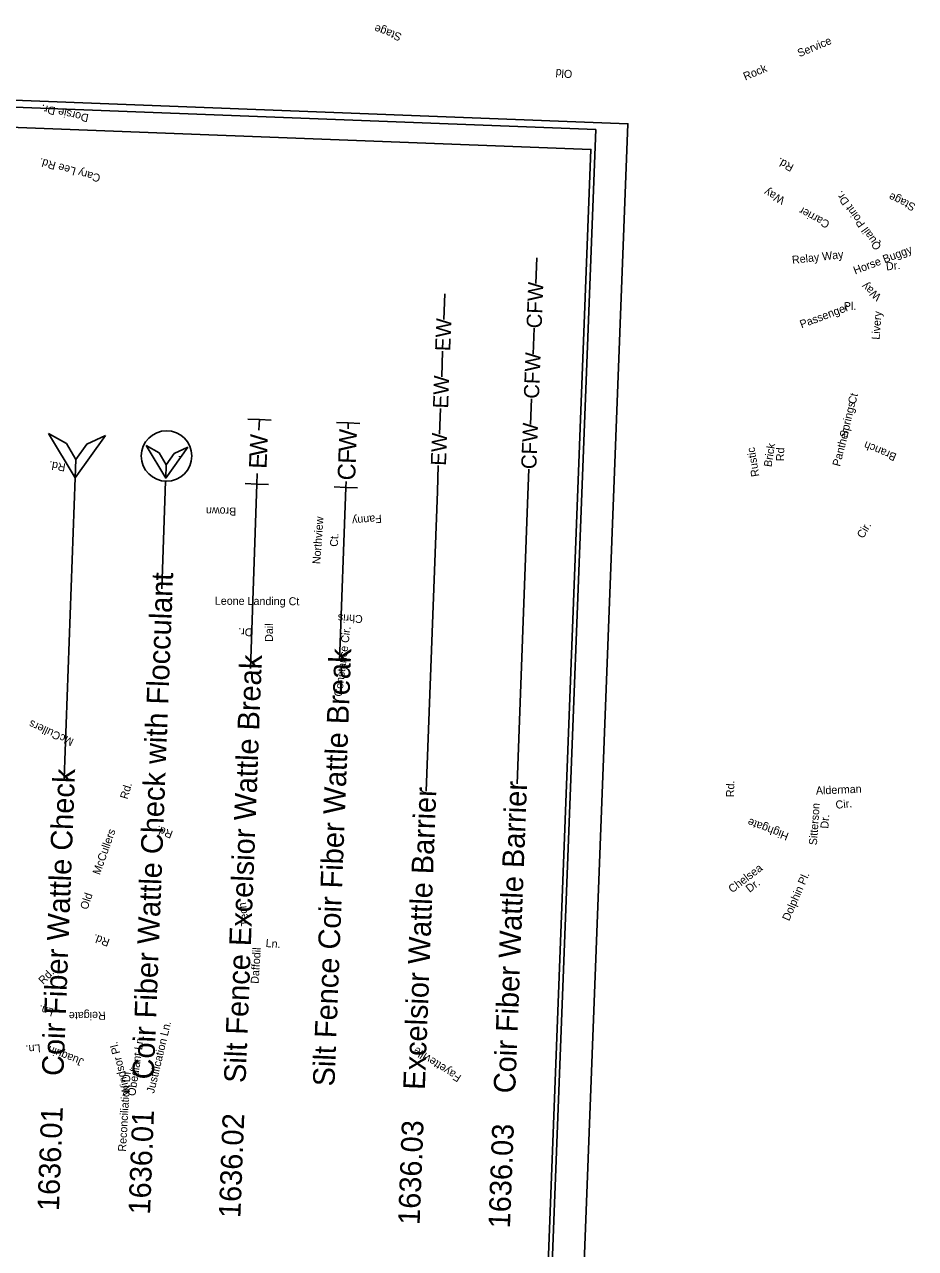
# Model space of a CAD drawing. Extents: x 1654773 to 2116434, y 680831 to 888488.
# Drawn here: x 2113644 to 2116434, y 697117 to 700949 of the extents above; entities that cross this region are included whole.
import ezdxf

# ---------------------------------------------------------------- set-up
doc = ezdxf.new("R2010")
doc.units = 0
for name, color, linetype in [('EC Title Sheet CELL', 7, 'Continuous'), ('Exist Road Non-System Type 51 Label', 7, 'Continuous'), ('Exist Road Primary US Label', 7, 'Continuous'), ('Exist Road Secondary Type 51 Label', 7, 'Continuous'), ('Old_Level_61', 7, 'Continuous'), ('Scratch_Level_6', 7, 'Continuous'), ('Sheet Plot Border Inside CELL', 7, 'Continuous'), ('Sheet Plot Border Outside CELL', 7, 'Continuous')]:
    doc.layers.add(name, color=color, linetype=linetype)

msp = doc.modelspace()

# ---------------------------------------------------------------- linework, layer by layer
at = {"layer": 'EC Title Sheet CELL'}
for p, q in [((2113767.7, 698588.4), (2113802.9, 699529.8)), ((2114073.8, 699182), (2114085.8, 699518.9)), ((2114352.1, 698932.5), (2114371.8, 699510)), ((2114630.7, 698956.7), (2114650.1, 699499.3)), ((2114901.9, 698548.4), (2114936.7, 699486.9)), ((2115186.1, 698571.4), (2115219.6, 699476.1))]:
    msp.add_line(p, q, dxfattribs=at)
at = {"layer": 'Old_Level_61'}
for p, q in [((2115244.7, 700137.3), (2115247.7, 700217.9)), ((2114957, 700024.8), (2114960, 700105.4)), ((2115236.3, 699916.9), (2115239.3, 699997.5)), ((2114950.3, 699845.5), (2114953.3, 699926.1)), ((2115228, 699696.5), (2115231, 699777.1)), ((2114943.5, 699666.2), (2114946.5, 699746.8)), ((2114936.7, 699486.9), (2114939.7, 699567.5)), ((2115219.6, 699476.1), (2115222.6, 699556.7))]:
    msp.add_line(p, q, dxfattribs=at)
at = {"layer": 'Scratch_Level_6'}
for p, q in [((2114379.5, 699711.6), (2114343, 699713)), ((2114378.2, 699678.7), (2114379.5, 699711.6)), ((2114379.5, 699711.6), (2114416.1, 699710.2)), ((2114657.8, 699701.1), (2114621.3, 699702.5)), ((2114657.1, 699682.8), (2114657.8, 699701.1)), ((2114657.8, 699701.1), (2114694.4, 699699.7)), ((2113728.9, 699657.5), (2113728.9, 699657.5)), ((2114032.1, 699622.4), (2114032.1, 699622.4)), ((2114129.3, 699596.8), (2114128.9, 699594.8)), ((2114371.8, 699510), (2114373, 699542.9)), ((2114371.8, 699510), (2114335.2, 699511.4)), ((2114371.8, 699510), (2114408.3, 699508.6)), ((2114650.1, 699499.3), (2114613.5, 699500.7)), ((2114650.1, 699499.3), (2114650.8, 699517.6)), ((2114650.1, 699499.3), (2114686.7, 699497.9))]:
    msp.add_line(p, q, dxfattribs=at)
for points in [[(2110171.4, 700758.7), (2109883.7, 693264.2), (2115129.9, 693062.9), (2115417.5, 700557.4)], [(2113719, 699668.3), (2113802.9, 699529.8), (2113805.1, 699586.3), (2113775, 699636.8)], [(2113897.2, 699661.4), (2113802.9, 699529.8), (2113805.1, 699586.3), (2113839, 699634.3)], [(2114024.8, 699630.3), (2114086.3, 699528.7), (2114087.9, 699570.2), (2114065.8, 699607.2)], [(2114155.5, 699625.2), (2114086.3, 699528.7), (2114087.9, 699570.2), (2114112.8, 699605.4)]]:
    msp.add_lwpolyline(points, close=True, dxfattribs=at)
msp.add_circle((2114088.8, 699597.8), 79, dxfattribs=at)
at = {"layer": 'Sheet Plot Border Inside CELL'}
msp.add_lwpolyline([(2115112.9, 692295.5), (2115432.4, 700619.3), (2110161.3, 700821.7), (2109841.8, 692497.8)], close=True, dxfattribs=at)
at = {"layer": 'Sheet Plot Border Outside CELL'}
msp.add_lwpolyline([(2115210.4, 692226.7), (2115533.2, 700638), (2110062.2, 700848), (2109739.4, 692436.7)], close=True, dxfattribs=at)

# ---------------------------------------------------------------- texts
at = {"layer": 'EC Title Sheet CELL'}
for s, height, p in [('CFW', 47.55, (2115263.1, 699996.6)), ('EW', 47.55, (2114977, 699925.2)), ('CFW', 47.55, (2115254.7, 699776.2)), ('EW', 47.55, (2114970.2, 699745.9)), ('CFW', 47.55, (2115246.4, 699555.8)), ('EW', 47.55, (2114963.5, 699566.6)), ('Coir Fiber Wattle Check with Flocculant', 67.828, (2114048.7, 697645)), ('Silt Fence Excelsior Wattle Break', 67.855, (2114336.2, 697634)), ('Silt Fence Coir Fiber Wattle Break', 67.855, (2114614.5, 697623.3)), ('Coir Fiber Wattle Check', 67.828, (2113765.8, 697655.9)), ('Coir Fiber Wattle Barrier', 67.855, (2115180.3, 697601.6)), ('Excelsior Wattle Barrier', 67.855, (2114897.4, 697612.5)), ('1636.01', 67.74, (2113751.8, 697233.1)), ('1636.01', 67.74, (2114037, 697222.2)), ('1636.02', 67.74, (2114319.8, 697211.3)), ('1636.03', 67.74, (2114881.1, 697189.8)), ('1636.03', 67.74, (2115163.9, 697178.9))]:
    msp.add_text(s, height=height, rotation=87.802, dxfattribs=at).set_placement(p)
at = {"layer": 'Exist Road Non-System Type 51 Label'}
for s, height, rotation, p in [('Dorsie Dr.', 25.05, 168.0297, (2113846.6, 700666.9)), ('Cary Lee Rd.', 25.049, 164.3667, (2113884, 700478)), ('Northview', 25.05, 86.0754, (2114570.1, 699258.6)), ('Cir.', 25.05, 59.5384, (2116270.1, 699337.6)), ('Ct.', 25.05, 86.9585, (2114625, 699313)), ('Constance Cir.', 25.049, 82.8196, (2114637.8, 698843.3)), ('Rd.', 25.05, 159.1046, (2114110.8, 698422.7)), ('Tech', 25.05, 98.2272, (2114347.7, 698127.8)), ('Justification Ln.', 25.049, 76.5682, (2114049.6, 697601)), ('Obediant Ln.', 25.049, 81.6544, (2113990.9, 697593.1)), ('Reconciliation Dr.', 25.049, 86.634, (2113961.6, 697419.5))]:
    msp.add_text(s, height=height, rotation=rotation, dxfattribs=at).set_placement(p)
at = {"layer": 'Exist Road Primary US Label'}
for s, height, rotation, p in [('Rd.', 25.05, 160.3905, (2113913, 698084.5)), ('Fayetteville', 25.049, 147.123, (2115013.8, 697657))]:
    msp.add_text(s, height=height, rotation=rotation, dxfattribs=at).set_placement(p)
at = {"layer": 'Exist Road Secondary Type 51 Label'}
for s, height, rotation, p in [('Stage', 25.05, 160.5208, (2114827, 700919.2)), ('Service', 25.05, 22.7007, (2116070.4, 700845.8)), ('Old', 25.05, 175.6094, (2115360, 700805.3)), ('Rock', 25.05, 22.6599, (2115900.8, 700773)), ('Rd.', 25.05, 151.8582, (2116055, 700508.3)), ('Way', 25.05, 151.992, (2116027.1, 700405.5)), ('Quail Point Dr.', 25.049, 125.5945, (2116328.5, 700253.3)), ('Stage', 25.05, 155.1463, (2116436.3, 700385.5)), ('Carrier', 25.05, 151.9919, (2116167.7, 700330.7)), ('Relay Way', 25.05, 6.5459, (2116048.4, 700198.9)), ('Horse Buggy', 25.049, 21.0114, (2116244.9, 700165.6)), ('Dr.', 25.05, 6.1311, (2116342.7, 700178.4)), ('Way', 25.05, 139.4258, (2116328.6, 700099.7)), ('Passenger', 25.05, 20.6597, (2116077, 699997.1)), ('Pl.', 25.05, 1.7565, (2116209.8, 700054)), ('Livery', 25.05, 85.5496, (2116321.1, 699961.1)), ('Springs', 25.05, 76.8967, (2116220, 699653.7)), ('Ct', 25.05, 75.9007, (2116245.9, 699758.5)), ('Panther', 25.05, 75.5941, (2116197.2, 699563.4)), ('Rustic', 25.05, 99.3114, (2115944.9, 699534.7)), ('Brick', 25.05, 81.021, (2115983, 699561.9)), ('Rd', 25.05, 88.702, (2116022, 699581.3)), ('Branch', 25.05, 157.2034, (2116376.6, 699603.7)), ('Rd.', 25.05, 170.7019, (2113774.1, 699573.7)), ('Brown', 25.05, 179.1898, (2114307.2, 699436.1)), ('Fanny', 25.05, 184.8667, (2114761.5, 699413.9)), ('Leone Landing Ct', 25.049, 359.6161, (2114239.9, 699132.1)), ('Chris', 25.05, 177.6846, (2114703.6, 699099.5)), ('Dr.', 25.05, 178.6829, (2114357.9, 699058)), ('Dail', 25.05, 89.5021, (2114421.7, 699015.7)), ('McCullers', 25.05, 155.6988, (2113800.4, 698710.9)), ('Rd.', 25.05, 88.865, (2115865.6, 698529.5)), ('Rd.', 25.05, 73.566, (2113966.3, 698521.6)), ('Alderman', 25.05, 2.3865, (2116122.3, 698537.7)), ('Sitterson', 25.05, 86.0321, (2116124.9, 698378.6)), ('Cir.', 25.05, 5.6725, (2116184.7, 698493.2)), ('Highgate', 25.05, 159.1223, (2116039, 698416.6)), (' Dr.', 25.05, 86.0321, (2116160.1, 698421.3)), ('McCullers', 25.05, 70.3677, (2113879.6, 698284.7)), ('Chelsea', 25.05, 37.3596, (2115859.8, 698228.7)), ('Dolphin Pl.', 25.049, 66.4792, (2116038.1, 698140.3)), ('Old', 25.05, 71.5022, (2113841, 698175.8)), (' Dr.', 25.05, 37.3596, (2115906.8, 698224.1)), ('Ln.', 25.05, 355.6584, (2114398.4, 698060.7)), ('Daffodil', 25.05, 86.2194, (2114376.7, 697944.9)), ('Rd.', 25.05, 45.6876, (2113702.6, 697941.7)), ('Ln.', 25.05, 163.7729, (2113737, 697866.6)), ('Reigate', 25.05, 180.4311, (2113898.2, 697858)), ('Ln.', 25.05, 184.146, (2113693.3, 697756)), ('Juaquin', 25.05, 158.6359, (2113831.9, 697709.4)), ('Windsor Pl.', 25.049, 104.2341, (2113976.1, 697600.2))]:
    msp.add_text(s, height=height, rotation=rotation, dxfattribs=at).set_placement(p)
at = {"layer": 'Scratch_Level_6'}
for s, height, p in [('W', 55.1, (2114403.3, 699595.4)), ('W', 55.2, (2114682.6, 699611.1)), ('F', 55.2, (2114681.1, 699572.8)), ('E', 55.1, (2114401.7, 699557.1)), ('C', 55.2, (2114679.1, 699520.5))]:
    msp.add_text(s, height=height, rotation=87.802, dxfattribs=at).set_placement(p)

doc.saveas('drawing.dxf')
